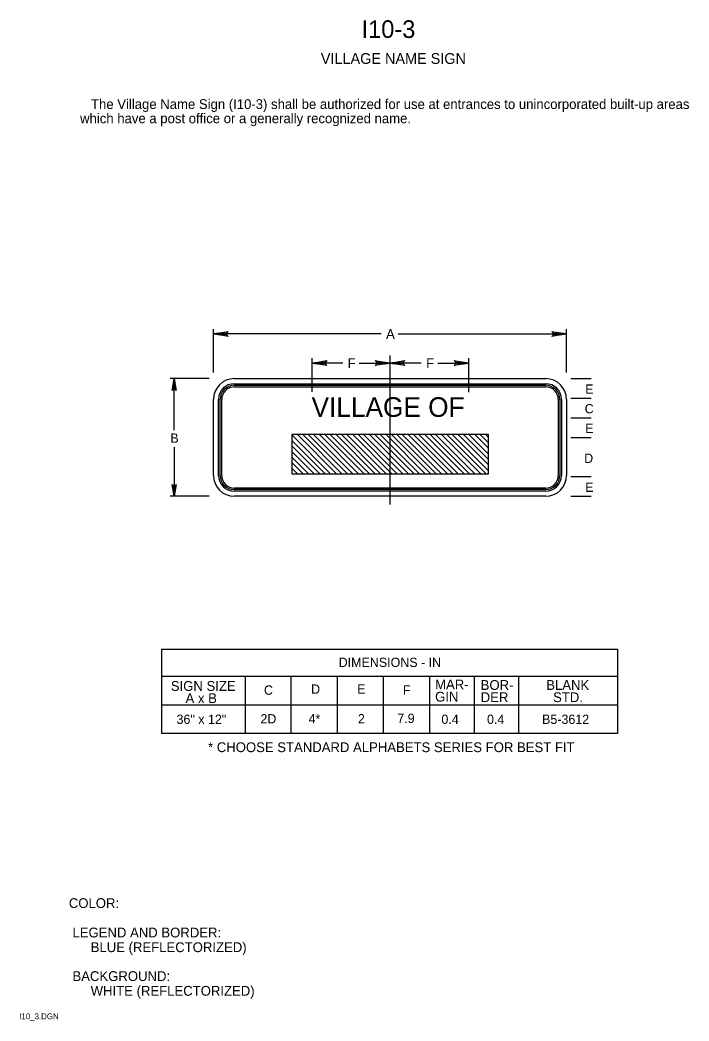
# Model space of a CAD drawing. Extents: x 0.013 to 0.183, y 0.004 to 0.259.
import ezdxf

# ---------------------------------------------------------------- set-up
doc = ezdxf.new("R2010")
doc.units = 0
for name, color, linetype in [('1', 7, 'Continuous'), ('2', 7, 'Continuous'), ('3', 7, 'Continuous')]:
    doc.layers.add(name, color=color, linetype=linetype)

# ---------------------------------------------------------------- blocks, each defined once
blk = doc.blocks.new('RARROW')
at = {"layer": '3'}
for p, q in [((-2.156, 0.285), (-2.2665, 0.384625)), ((-2.2665, 0.384625), (0, 0)), ((0, 0), (-2.2665, -0.379125)), ((-2.156, 0.285), (-2.075625, 0.12075)), ((0, 0), (-2.156, 0.285)), ((-2.14975, -0.2705), (0, 0)), ((-2.075625, 0.12075), (0, 0)), ((0, 0), (-2.074, -0.108)), ((-2.2665, -0.379125), (-2.14975, -0.2705)), ((-2.074, -0.108), (-2.14975, -0.2705))]:
    blk.add_line(p, q, dxfattribs=at)

msp = doc.modelspace()

# ---------------------------------------------------------------- linework, layer by layer
at = {"layer": '1'}
msp.add_line((0.107, 0.17362), (0.107, 0.13562), dxfattribs=at)
at = {"layer": '3'}
for p, q in [((0.062, 0.1693), (0.062, 0.18038)), ((0.10475, 0.17913), (0.062, 0.17913)), ((0.10912, 0.17913), (0.152, 0.17913)), ((0.152, 0.1693), (0.152, 0.18038)), ((0.08713, 0.16439), (0.08713, 0.17296)), ((0.09496, 0.17171), (0.08713, 0.17171)), ((0.09917, 0.17171), (0.107, 0.17171)), ((0.107, 0.17233), (0.107, 0.17046)), ((0.11496, 0.17171), (0.107, 0.17171)), ((0.11917, 0.17171), (0.12713, 0.17171)), ((0.12713, 0.16429), (0.12713, 0.17296)), ((0.06087, 0.16775), (0.051, 0.16775)), ((0.052, 0.15463), (0.052, 0.16775)), ((0.0673, 0.16775), (0.1467, 0.16775)), ((0.0673, 0.16645), (0.1467, 0.16645)), ((0.0673, 0.16605), (0.1467, 0.16605)), ((0.15313, 0.16775), (0.15825, 0.16775)), ((0.0673, 0.16565), (0.1467, 0.16565)), ((0.062, 0.14305), (0.062, 0.16245)), ((0.0633, 0.14305), (0.0633, 0.16245)), ((0.0637, 0.14305), (0.0637, 0.16245)), ((0.0641, 0.14305), (0.0641, 0.16245)), ((0.1499, 0.16245), (0.1499, 0.14305)), ((0.1503, 0.16245), (0.1503, 0.14305)), ((0.1507, 0.16245), (0.1507, 0.14305)), ((0.152, 0.16245), (0.152, 0.14305)), ((0.15313, 0.16275), (0.15825, 0.16275)), ((0.15313, 0.15775), (0.15825, 0.15775)), ((0.082, 0.15338), (0.09187, 0.1435)), ((0.08338, 0.1535), (0.09337, 0.1435)), ((0.08475, 0.1535), (0.09475, 0.1435)), ((0.08613, 0.1535), (0.09613, 0.1435)), ((0.0875, 0.1535), (0.0975, 0.1435)), ((0.089, 0.1535), (0.099, 0.1435)), ((0.09037, 0.1535), (0.10038, 0.1435)), ((0.09175, 0.1535), (0.10175, 0.1435)), ((0.09325, 0.1535), (0.10325, 0.1435)), ((0.09463, 0.1535), (0.10462, 0.1435)), ((0.096, 0.1535), (0.106, 0.1435)), ((0.0975, 0.1535), (0.1075, 0.1435)), ((0.09888, 0.1535), (0.10887, 0.1435)), ((0.10025, 0.1535), (0.11025, 0.1435)), ((0.10175, 0.1535), (0.11175, 0.1435)), ((0.10313, 0.1535), (0.11313, 0.1435)), ((0.1045, 0.1535), (0.1145, 0.1435)), ((0.106, 0.1535), (0.116, 0.1435)), ((0.10737, 0.1535), (0.11738, 0.1435)), ((0.10875, 0.1535), (0.11875, 0.1435)), ((0.11013, 0.1535), (0.12012, 0.1435)), ((0.11163, 0.1535), (0.12162, 0.1435)), ((0.113, 0.1535), (0.123, 0.1435)), ((0.11438, 0.1535), (0.12437, 0.1435)), ((0.11588, 0.1535), (0.12588, 0.1435)), ((0.11725, 0.1535), (0.12725, 0.1435)), ((0.11863, 0.1535), (0.12862, 0.1435)), ((0.12012, 0.1535), (0.13012, 0.1435)), ((0.1215, 0.1535), (0.1315, 0.1435)), ((0.12287, 0.1535), (0.13212, 0.14425)), ((0.12437, 0.1535), (0.13212, 0.14575)), ((0.12575, 0.1535), (0.13212, 0.14713)), ((0.12713, 0.1535), (0.13212, 0.1485)), ((0.12862, 0.1535), (0.13212, 0.15)), ((0.13, 0.1535), (0.13212, 0.15138)), ((0.13137, 0.1535), (0.13212, 0.15275)), ((0.082, 0.152), (0.0905, 0.1435)), ((0.082, 0.15063), (0.08912, 0.1435)), ((0.15313, 0.15275), (0.15825, 0.15275)), ((0.052, 0.15025), (0.052, 0.13775)), ((0.082, 0.14913), (0.08763, 0.1435)), ((0.082, 0.14775), (0.08625, 0.1435)), ((0.082, 0.14638), (0.08488, 0.1435)), ((0.082, 0.14488), (0.08338, 0.1435)), ((0.082, 0.1435), (0.082, 0.1435)), ((0.15313, 0.14275), (0.15825, 0.14275)), ((0.1467, 0.13985), (0.0673, 0.13985)), ((0.1467, 0.13945), (0.0673, 0.13945)), ((0.1467, 0.13905), (0.0673, 0.13905)), ((0.06087, 0.13775), (0.051, 0.13775)), ((0.1467, 0.13775), (0.0673, 0.13775)), ((0.15313, 0.13775), (0.15825, 0.13775)), ((0.04875, 0.09875), (0.165, 0.09875)), ((0.04875, 0.09875), (0.04875, 0.07725)), ((0.165, 0.09875), (0.165, 0.07725)), ((0.07004, 0.0919), (0.07004, 0.07727)), ((0.12842, 0.0919), (0.12842, 0.07727)), ((0.13979, 0.0919), (0.13979, 0.07727)), ((0.165, 0.09175), (0.04875, 0.09175)), ((0.08175, 0.09175), (0.08175, 0.07725)), ((0.0935, 0.09175), (0.0935, 0.07725)), ((0.10525, 0.09175), (0.10525, 0.07725)), ((0.11704, 0.09175), (0.11704, 0.07727)), ((0.165, 0.0845), (0.04875, 0.0845)), ((0.165, 0.07725), (0.04875, 0.07725))]:
    msp.add_line(p, q, dxfattribs=at)
msp.add_lwpolyline([(0.13212, 0.1535), (0.082, 0.1535), (0.082, 0.1435), (0.13212, 0.1435)], close=True, dxfattribs=at)
for centre, radius, start, end in [((0.0673, 0.16245), 0.0053, 90, 180), ((0.0673, 0.16245), 0.004, 90, 180), ((0.0673, 0.16245), 0.0036, 90, 180), ((0.1467, 0.16245), 0.0053, 0, 90), ((0.1467, 0.16245), 0.004, 0, 90), ((0.1467, 0.16245), 0.0036, 0, 90), ((0.0673, 0.16245), 0.0032, 90, 180), ((0.1467, 0.16245), 0.0032, 0, 90), ((0.0673, 0.14305), 0.0053, 180, 270), ((0.0673, 0.14305), 0.004, 180, 270), ((0.0673, 0.14305), 0.0036, 180, 270), ((0.0673, 0.14305), 0.0032, 180, 270), ((0.1467, 0.14305), 0.0053, 270, 0), ((0.1467, 0.14305), 0.004, 270, 0), ((0.1467, 0.14305), 0.0036, 270, 0), ((0.1467, 0.14305), 0.0032, 270, 0)]:
    msp.add_arc(centre, radius, start, end, dxfattribs=at)

# ---------------------------------------------------------------- block references
for p, xscale, yscale, rotation in [((0.062, 0.17913), 0.0016545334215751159, 0.0016366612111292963, 180), ((0.08713, 0.17171), 0.0016545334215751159, 0.0016366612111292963, 180), ((0.107, 0.17171), 0.0016545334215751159, 0.0016366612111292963, 180), ((0.052, 0.16775), 0.0013236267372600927, 0.001309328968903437, 90), ((0.052, 0.13775), 0.0013236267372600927, 0.001309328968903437, -90)]:
    msp.add_blockref('RARROW', p, dxfattribs=dict(at, xscale=xscale, yscale=yscale, rotation=rotation))
at = {"layer": '3', "xscale": 0.0016545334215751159, "yscale": 0.0016366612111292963}
for p in [(0.152, 0.17913), (0.107, 0.17171), (0.12713, 0.17171)]:
    msp.add_blockref('RARROW', p, dxfattribs=at)

# ---------------------------------------------------------------- texts
at = {"layer": '1'}
for s, height, p in [('I10-3', 0.0045, (0.09975, 0.25462)), ('VILLAGE NAME SIGN', 0.0027503, (0.08937, 0.248)), ('COLOR:', 0.0025, (0.02513, 0.03275)), (' LEGEND AND BORDER:', 0.0024998, (0.02513, 0.02525)), ('      BLUE (REFLECTORIZED)', 0.0024998, (0.02513, 0.0215)), (' BACKGROUND:', 0.0024998, (0.02513, 0.01413)), ('      WHITE (REFLECTORIZED)', 0.0024998, (0.02513, 0.01038)), ('I10_3.DGN', 0.0015, (0.0125, 0.00438))]:
    msp.add_text(s, height=height, dxfattribs=at).set_placement(p)
at = {"layer": '2'}
for s, height, p in [('   The Village Name Sign (I10-3) shall be authorized for use at entrances to unincorporated built-up areas', 0.00249975, (0.028, 0.2365)), ('which have a post office or a generally recognized name.', 0.0024998, (0.028, 0.23287))]:
    msp.add_text(s, height=height, dxfattribs=at).set_placement(p)
at = {"layer": '3'}
for s, height, p in [('A', 0.0025, (0.106, 0.17788)), ('F', 0.0025, (0.09621, 0.17046)), ('F', 0.0025, (0.11621, 0.17046)), ('E', 0.00238, (0.15675, 0.16387)), ('VILLAGE OF', 0.005, (0.087, 0.158)), ('C', 0.00238, (0.15663, 0.15888)), ('E', 0.00238, (0.15675, 0.15388)), ('B', 0.00238, (0.051, 0.15138)), ('D', 0.00238, (0.1565, 0.14625)), ('E', 0.00238, (0.15675, 0.13887)), ('DIMENSIONS - IN', 0.0023752, (0.09392, 0.09421)), ('SIGN SIZE', 0.0025, (0.05113, 0.08812)), ('C', 0.00238, (0.07487, 0.08713)), ('D', 0.00238, (0.08688, 0.08738)), ('E', 0.00238, (0.09863, 0.08738)), ('F', 0.00238, (0.11031, 0.08713)), ('MAR-', 0.0025, (0.1185, 0.0885)), ('BOR-', 0.0025, (0.13012, 0.08837)), ('BLANK', 0.0025, (0.14683, 0.08837)), ('A x B', 0.0025, (0.05488, 0.085)), ('GIN', 0.0025, (0.1185, 0.08538)), ('DER', 0.0025, (0.13012, 0.08525)), ('STD.', 0.0025, (0.14858, 0.08525)), ('36" x 12"', 0.002375, (0.05259, 0.07969)), ('2D', 0.002375, (0.07397, 0.07981)), ('4*', 0.002375, (0.08624, 0.07981)), ('2', 0.00238, (0.09882, 0.07981)), ('7.9', 0.002375, (0.10887, 0.07994)), ('0.4', 0.002375, (0.12011, 0.07969)), ('0.4', 0.002375, (0.13173, 0.07969)), ('B5-3612', 0.002375, (0.14577, 0.07969)), ('* CHOOSE STANDARD ALPHABETS SERIES FOR BEST FIT', 0.0024998, (0.06062, 0.0725))]:
    msp.add_text(s, height=height, dxfattribs=at).set_placement(p)

doc.saveas('drawing.dxf')
